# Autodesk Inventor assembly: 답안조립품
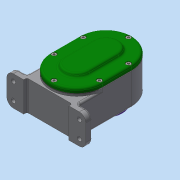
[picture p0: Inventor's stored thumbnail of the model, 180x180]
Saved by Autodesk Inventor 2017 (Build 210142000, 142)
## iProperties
Part Number: 답안조립품
Material: 일반
Document SubType Name: Assembly
Designer: MRC
Author: MRC
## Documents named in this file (19)
- C:\Users\MRC\Documents\Inventor\710609V1016\답안조립품.iam
- C:\Users\MRC\Desktop\710609V1016\스퍼기어 A.ipt
- C:\Users\MRC\Desktop\710609V1016\스퍼기어 B.ipt
- C:\Users\MRC\Desktop\710609V1016\오일 실 12 22 7.ipt
- C:\Users\MRC\Desktop\710609V1016\축 A.ipt
- C:\Users\MRC\Desktop\710609V1016\축 B.ipt
- C:\Users\MRC\Desktop\710609V1016\칼라.ipt
- C:\Users\MRC\Desktop\710609V1016\커버 A.ipt
- C:\Users\MRC\Desktop\710609V1016\커버 B.ipt
- C:\Users\MRC\Desktop\710609V1016\키 4 x 4 x 12.ipt
- C:\Users\MRC\Desktop\710609V1016\키 5 x 5 x 12.ipt
- C:\Users\MRC\Desktop\710609V1016\개스킷 A.ipt
- C:\Users\MRC\Desktop\710609V1016\개스킷 B.ipt
- C:\Users\MRC\Desktop\710609V1016\베어링 6001.ipt
- 베어링 6001.ipt
- C:\Users\MRC\Desktop\710609V1016\베어링 6002.ipt
- 베어링 6002.ipt
- C:\Users\MRC\Desktop\710609V1016\볼트 M4.ipt
- C:\Users\MRC\Desktop\710609V1016\본체.ipt
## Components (2 placed, 2 different names)
1. 개스킷 A:1
2. 개스킷 B:1
